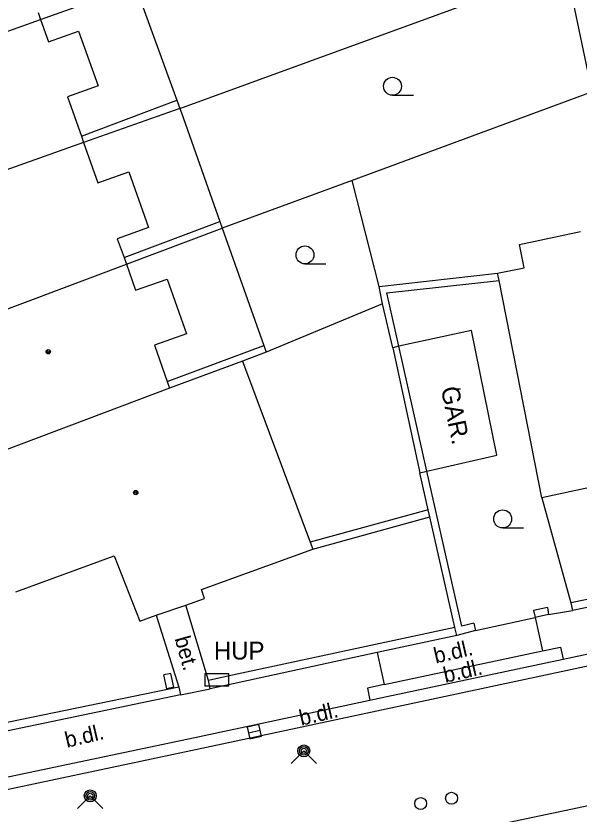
# Model space of a CAD drawing. Extents: x -596229 to -595156, y -1161237 to -1159376.
# Drawn here: x -595911.22 to -595887.66, y -1161024.38 to -1160991.01 of the extents above; entities that cross this region are included whole.
import ezdxf

# ---------------------------------------------------------------- set-up
doc = ezdxf.new("R2010")
doc.units = 0
for name, color, linetype in [('DOP - kresba z DSPS bez souradnic', 7, 'Continuous'), ('DOP - rozhrani ploch obecne', 7, 'Continuous'), ('Level 24', 7, 'Continuous'), ('Level 27', 7, 'Continuous'), ('Level 28', 7, 'Continuous'), ('Level 31', 7, 'Continuous'), ('Level 36', 7, 'Continuous'), ('Level 39', 7, 'Continuous'), ('silnoproud - povrch.  znaky a  RIS  skut. velikost', 7, 'Continuous'), ('TM - budovy zdene_ betonove - VP', 7, 'Continuous'), ('TM - chodniky - VP', 7, 'Continuous'), ('TM - komunikace - VP', 7, 'Continuous'), ('TM - letecke snimky - pomocna linie', 7, 'Continuous'), ('TM - plot drateny_ kovovy - VP', 7, 'Continuous'), ('TM - podezdivka plotu - VP', 7, 'Continuous'), ('TM - popis objektu', 7, 'Continuous'), ('TM - popis povrchu', 7, 'Continuous'), ('TM - rozhrani ploch obecne - VP', 7, 'Continuous'), ('TM - vjezd na pozemek', 7, 'Continuous'), ('TM - vstup do budovy - zdene_ betonove', 7, 'Continuous')]:
    doc.layers.add(name, color=color, linetype=linetype)

msp = doc.modelspace()

# ---------------------------------------------------------------- linework, layer by layer
at = {"layer": 'DOP - kresba z DSPS bez souradnic'}
for points in [[(-595908.48, -1160996.04), (-595904.49, -1160994.53)], [(-595906.7, -1161001.11), (-595902.69, -1160999.6)], [(-595904.89, -1161006.29), (-595900.85, -1161004.79)]]:
    msp.add_lwpolyline(points, dxfattribs=at)
at = {"layer": 'DOP - rozhrani ploch obecne'}
for points in [[(-595904.36, -1160994.88), (-595888.2, -1160988.99)], [(-595887.11, -1160994.18), (-595888.2, -1160988.99)], [(-595910.19, -1160991.16), (-595906.23, -1160989.74)], [(-595906.23, -1160989.74), (-595904.49, -1160994.53)], [(-595887.11, -1160994.18), (-595897.16, -1160997.89)], [(-595904.49, -1160994.53), (-595904.36, -1160994.88)], [(-595904.36, -1160994.88), (-595908.39, -1160996.3)], [(-595904.36, -1160994.88), (-595904.29, -1160995.06)], [(-595904.29, -1160995.06), (-595902.69, -1160999.6)], [(-595897.16, -1160997.89), (-595902.59, -1160999.88)], [(-595896.02, -1161002.32), (-595897.16, -1160997.89)], [(-595902.69, -1160999.6), (-595902.59, -1160999.88)], [(-595906.6, -1161001.39), (-595902.59, -1160999.88)], [(-595902.59, -1160999.88), (-595900.85, -1161004.79)], [(-595895.88, -1161003.04), (-595900.75, -1161005.07)], [(-595900.85, -1161004.79), (-595900.75, -1161005.07)], [(-595900.75, -1161005.07), (-595901.75, -1161005.44)]]:
    msp.add_lwpolyline(points, dxfattribs=at)
at = {"layer": 'Level 24'}
msp.add_lwpolyline([(-595903.318, -1161019.019), (-595902.318, -1161019.019), (-595902.318, -1161018.519), (-595903.318, -1161018.519)], close=True, dxfattribs=at)
at = {"layer": 'Level 27'}
msp.add_line((-595901.494, -1161020.986), (-595901.006, -1161020.874), dxfattribs=at)
msp.add_lwpolyline([(-595901.437, -1161021.23), (-595900.95, -1161021.117), (-595901.063, -1161020.63), (-595901.55, -1161020.743)], close=True, dxfattribs=at)
at = {"layer": 'Level 28'}
for centre in [(-595894.29, -1161023.94), (-595893, -1161023.72)]:
    msp.add_circle(centre, 0.25, dxfattribs=at)
at = {"layer": 'Level 31'}
for points in [[(-595899.71, -1161022.27), (-595899.18, -1161021.74), (-595898.65, -1161022.27)], [(-595908.64, -1161024.15), (-595908.11, -1161023.62), (-595907.58, -1161024.15)]]:
    msp.add_lwpolyline(points, dxfattribs=at)
for centre, radius in [((-595899.18, -1161021.74), 0.25), ((-595899.18, -1161021.74), 0.18), ((-595899.18, -1161021.74), 0.11), ((-595908.11, -1161023.62), 0.25), ((-595908.11, -1161023.62), 0.18), ((-595908.11, -1161023.62), 0.11)]:
    msp.add_circle(centre, radius, dxfattribs=at)
at = {"layer": 'Level 36'}
for p, q in [((-595895.47, -1160994.325), (-595894.595, -1160994.325)), ((-595899.13, -1161001.375), (-595898.255, -1161001.375)), ((-595890.86, -1161012.415), (-595889.985, -1161012.415))]:
    msp.add_line(p, q, dxfattribs=at)
for centre in [(-595895.47, -1160993.95), (-595899.13, -1161001), (-595890.86, -1161012.04)]:
    msp.add_circle(centre, 0.375, dxfattribs=at)
at = {"layer": 'Level 39'}
msp.add_line((-595893.13, -1161006.6), (-595892.63, -1161006.6), dxfattribs=at)
for centre, radius in [((-595909.87, -1161005.05), 0.09), ((-595909.87, -1161005.05), 0.0398), ((-595906.21, -1161010.94), 0.09), ((-595906.21, -1161010.94), 0.0398)]:
    msp.add_circle(centre, radius, dxfattribs=at)
at = {"layer": 'silnoproud - povrch.  znaky a  RIS  skut. velikost'}
for points in [[(-595904.74, -1161018.5), (-595905.03, -1161018.56)], [(-595904.91, -1161019.14), (-595905.03, -1161018.56)], [(-595904.61, -1161019.08), (-595904.74, -1161018.5)], [(-595904.61, -1161019.08), (-595904.91, -1161019.14)]]:
    msp.add_lwpolyline(points, dxfattribs=at)
at = {"layer": 'TM - budovy zdene_ betonove - VP'}
for points in [[(-595910.29, -1160990.87), (-595910.19, -1160991.16)], [(-595918.61, -1160994.17), (-595910.19, -1160991.16)], [(-595910.19, -1160991.16), (-595909.86, -1160992.09)], [(-595909.86, -1160992.09), (-595908.6, -1160991.64)], [(-595908.6, -1160991.64), (-595907.78, -1160993.93)], [(-595907.78, -1160993.93), (-595909.06, -1160994.39)], [(-595909.06, -1160994.39), (-595908.48, -1160996.04)], [(-595908.39, -1160996.3), (-595916.79, -1160999.28)], [(-595908.48, -1160996.04), (-595908.39, -1160996.3)], [(-595908.39, -1160996.3), (-595907.8, -1160997.99)], [(-595907.8, -1160997.99), (-595906.5, -1160997.53)], [(-595906.5, -1160997.53), (-595905.67, -1160999.86)], [(-595905.67, -1160999.86), (-595906.98, -1161000.33)], [(-595890.15, -1161000.56), (-595887.61, -1161000.02)], [(-595906.98, -1161000.33), (-595906.7, -1161001.11)], [(-595889.96, -1161001.54), (-595890.15, -1161000.56)], [(-595906.7, -1161001.11), (-595906.6, -1161001.39)], [(-595914.95, -1161004.53), (-595906.6, -1161001.39)], [(-595906.6, -1161001.39), (-595906.22, -1161002.48)], [(-595891.07, -1161001.76), (-595889.96, -1161001.54)], [(-595906.22, -1161002.48), (-595904.9, -1161002.01)], [(-595904.9, -1161002.01), (-595904.08, -1161004.3)], [(-595891.01, -1161002.07), (-595891.07, -1161001.76)], [(-595889.22, -1161011.16), (-595891.01, -1161002.07)], [(-595904.08, -1161004.3), (-595905.42, -1161004.77)], [(-595892.16, -1161004.16), (-595895.21, -1161004.82)], [(-595891.1, -1161009.38), (-595892.16, -1161004.16)], [(-595905.42, -1161004.77), (-595904.89, -1161006.29)], [(-595894.03, -1161010.04), (-595895.21, -1161004.82)], [(-595901.75, -1161005.44), (-595904.79, -1161006.57)], [(-595901.75, -1161005.44), (-595898.91, -1161013.01)], [(-595904.89, -1161006.29), (-595904.79, -1161006.57)], [(-595904.79, -1161006.57), (-595913.12, -1161009.71)], [(-595894.03, -1161010.04), (-595891.1, -1161009.38)], [(-595883.86, -1161010), (-595889.22, -1161011.16)], [(-595898.91, -1161013.01), (-595898.8, -1161013.3)], [(-595903.46, -1161014.99), (-595898.8, -1161013.3)], [(-595911.22, -1161015.09), (-595907.11, -1161013.58)], [(-595907.11, -1161013.58), (-595906.04, -1161016.31)], [(-595903.33, -1161015.37), (-595903.46, -1161014.99)], [(-595904.11, -1161015.64), (-595903.33, -1161015.37)], [(-595906.04, -1161016.31), (-595905.36, -1161016.07)]]:
    msp.add_lwpolyline(points, dxfattribs=at)
at = {"layer": 'TM - chodniky - VP'}
for points in [[(-595903.16, -1161018.8), (-595904.11, -1161015.64)], [(-595905.36, -1161016.07), (-595904.41, -1161019.08)]]:
    msp.add_lwpolyline(points, dxfattribs=at)
at = {"layer": 'TM - komunikace - VP'}
for points in [[(-595888.33, -1161017.91), (-595883.75, -1161016.93)], [(-595896.41, -1161019.62), (-595895.7, -1161019.47), (-595888.33, -1161017.91)], [(-595914.09, -1161023.36), (-595903.54, -1161021.14), (-595896.41, -1161019.62)], [(-595885.43, -1161023.65), (-595892.64, -1161025.17)]]:
    msp.add_lwpolyline(points, dxfattribs=at)
at = {"layer": 'TM - letecke snimky - pomocna linie'}
msp.add_lwpolyline([(-595889.22, -1161011.16), (-595888.01, -1161015.55)], dxfattribs=at)
at = {"layer": 'TM - plot drateny_ kovovy - VP'}
for points in [[(-595895.71, -1161002.59), (-595891.01, -1161002.07)], [(-595895.21, -1161004.82), (-595895.71, -1161002.59)], [(-595892.57, -1161016.52), (-595894.03, -1161010.04)], [(-595885.49, -1161015.04), (-595888.01, -1161015.55)], [(-595904.41, -1161019.08), (-595916.27, -1161021.51), (-595918.18, -1161015.98)], [(-595888.99, -1161015.75), (-595889.57, -1161015.87)], [(-595892.86, -1161016.58), (-595902.35, -1161018.62), (-595903.16, -1161018.8)], [(-595892.06, -1161016.4), (-595892.57, -1161016.52)]]:
    msp.add_lwpolyline(points, dxfattribs=at)
at = {"layer": 'TM - podezdivka plotu - VP'}
for points in [[(-595896.02, -1161002.32), (-595891.07, -1161001.76)], [(-595895.88, -1161003.04), (-595896.02, -1161002.32)], [(-595895.46, -1161004.88), (-595895.88, -1161003.04)], [(-595895.21, -1161004.82), (-595895.46, -1161004.88)], [(-595894.32, -1161010.11), (-595894.03, -1161010.04)], [(-595893.97, -1161011.66), (-595894.32, -1161010.11)], [(-595893.91, -1161011.95), (-595893.97, -1161011.66)], [(-595892.86, -1161016.58), (-595893.91, -1161011.95)], [(-595882.54, -1161014.77), (-595887.94, -1161015.87)], [(-595888.01, -1161015.55), (-595887.94, -1161015.87)], [(-595889.57, -1161015.87), (-595889.5, -1161016.16)], [(-595888.94, -1161016.03), (-595889.5, -1161016.16)], [(-595888.99, -1161015.75), (-595888.94, -1161016.03)], [(-595892.78, -1161016.91), (-595892.86, -1161016.58)], [(-595891.99, -1161016.71), (-595892.78, -1161016.91)], [(-595892.06, -1161016.4), (-595891.99, -1161016.71)], [(-595892.78, -1161016.91), (-595896.11, -1161017.62)], [(-595896.11, -1161017.62), (-595903.09, -1161019.14)], [(-595903.09, -1161019.14), (-595903.12, -1161019), (-595903.16, -1161018.8)], [(-595904.41, -1161019.08), (-595904.34, -1161019.4)], [(-595904.34, -1161019.4), (-595916.37, -1161021.9)]]:
    msp.add_lwpolyline(points, dxfattribs=at)
at = {"layer": 'TM - rozhrani ploch obecne - VP'}
for points in [[(-595895.46, -1161004.88), (-595894.32, -1161010.11)], [(-595893.97, -1161011.66), (-595898.91, -1161013.01)], [(-595898.8, -1161013.3), (-595893.91, -1161011.95)], [(-595889.5, -1161016.16), (-595889.2, -1161017.56)], [(-595883.75, -1161016.93), (-595883.65, -1161017.42), (-595903.45, -1161021.64), (-595913.98, -1161023.87), (-595914.09, -1161023.36)], [(-595896.11, -1161017.62), (-595895.82, -1161018.96)], [(-595895.82, -1161018.96), (-595889.2, -1161017.56)], [(-595889.2, -1161017.56), (-595888.44, -1161017.4), (-595888.33, -1161017.91)], [(-595895.82, -1161018.96), (-595896.51, -1161019.11), (-595896.41, -1161019.62)]]:
    msp.add_lwpolyline(points, dxfattribs=at)
at = {"layer": 'TM - vjezd na pozemek'}
for points in [[(-595888.94, -1161016.03), (-595887.94, -1161015.87)], [(-595891.99, -1161016.71), (-595889.5, -1161016.16)], [(-595904.34, -1161019.4), (-595903.09, -1161019.14)]]:
    msp.add_lwpolyline(points, dxfattribs=at)
at = {"layer": 'TM - vstup do budovy - zdene_ betonove'}
msp.add_lwpolyline([(-595905.36, -1161016.07), (-595904.11, -1161015.64)], dxfattribs=at)

# ---------------------------------------------------------------- texts
at = {"layer": 'TM - popis objektu'}
msp.add_text('GAR.', height=0.75, rotation=281.5272, dxfattribs=at).set_placement((-595893.45, -1161006.58))
msp.add_text('HUP', height=0.75, dxfattribs=at).set_placement((-595902.94, -1161017.92))
at = {"layer": 'TM - popis povrchu'}
for s, rotation, p in [('bet.', 285.9248, (-595904.59, -1161017.04)), ('b.dl.', 13.11, (-595893.66, -1161018.09)), ('b.dl.', 13.11, (-595893.26, -1161018.9)), ('b.dl.', 13.11, (-595899.29, -1161020.69)), ('b.dl.', 13.11, (-595909.09, -1161021.61))]:
    msp.add_text(s, height=0.65, rotation=rotation, dxfattribs=at).set_placement(p)

doc.saveas('drawing.dxf')
